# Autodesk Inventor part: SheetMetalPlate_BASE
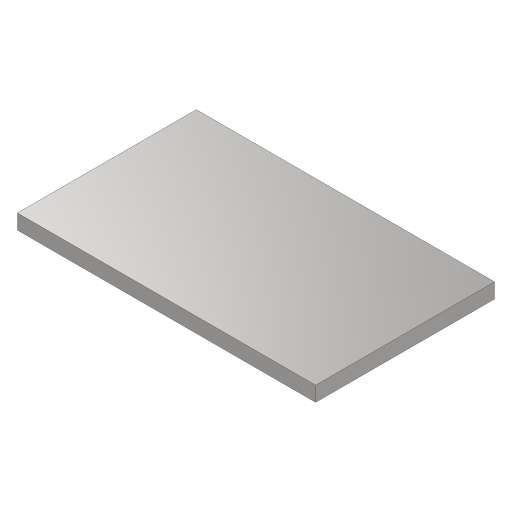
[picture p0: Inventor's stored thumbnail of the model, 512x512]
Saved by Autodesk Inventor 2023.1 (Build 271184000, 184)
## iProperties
Created: 2022-08
Part Number: SheetMetalPlate_BASE
Material: Steel
Document SubType Name: Sheet Metal
Designer: F.Stasiak
Density: 7.85 g/cm^3
Sheet Metal Rule: Steel 2.5 mm/Round
Appearance: Stainless - Brushed
Catalog Web Link: www.expertbooks.eu
Category: Autodesk® Inventor® Tutorial Series
Company: Fabian Stasiak CAD Consulting
Author: F.Stasiak
Subject: Sheet Metal Design. Basic and Advanced techniques
Thickness: 2,5
FLATAREA: =<FLAT PATTERN AREA>
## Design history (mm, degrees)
node "Face1"
  sketch "Sketch1"
    geometry: L1 (25, -15)-(-25, -15); L2 (-25, -15)-(-25, 15); L3 (-25, 15)-(25, 15); L4 (25, 15)-(25, -15); L5 (25, -15)-(-25, 15); L6 (-25, -15)-(25, 15); 1 further point
    constraints: 12 end point, 2 midpoint, 2 parallel, 1 horizontal, 1 perpendicular
    dimensions: "d0" = 50 distance of L2.end L3.end; "d1" = 30 distance of L1.end L2.end
body "Solid1"
face "Plate1" dims "d2" = 2.5 (= Thickness)
other parameters: "Thickness" = 2.5 (derived), "BendRadius" = 2.5 (= Thickness), "BendReliefWidth" = 2.5 (= Thickness), "BendReliefDepth" = 1.25 (= 0.5 x Thickness), "SeamGap" = 0.01, "MinimumRemnant" = 5 (= 2 x Thickness), "TransitionRadius" = 2.5 (= BendRadius), "JacobiRadiusSize" = 2.5 (= BendRadius), "GapSize" = 2.5 (= Thickness), "WIDTH" = 15 [user parameter], "ANGLE" = 120 deg [user parameter]
